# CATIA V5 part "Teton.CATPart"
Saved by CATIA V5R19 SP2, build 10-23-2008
Part number: Teton
Bounding box of the stored display mesh (mm): x 0 to 30, y -3.324 to 3.324, z -3.161 to 3.161
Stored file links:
  D:\SCHOOL\FRANCE\BANC_POUTRE_EN_MOUSSE\Teton.CATPart
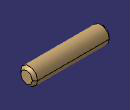
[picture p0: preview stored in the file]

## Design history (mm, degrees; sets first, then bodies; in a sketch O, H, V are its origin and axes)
AxisSystem1: origin (0, 0, 0), X (1, 0, 0), Y (0, 1, 0), Z (0, 0, 1)
Body1 (main body)
  Sketch1 on YZ plane of AxisSystem1, origin (0, 0, 0), H (0, 1, 0), V (0, 0, 1)
    circle A1 centre (0, 0) radius 3.324
    radius A1 = 3.324
  Pad1: profile Sketch1, direction (1, 0, 0), length 30
  Chamfer1: length 1, angle 45, on edge [face of Pad1 from Sketch1.A1 | end face of Pad1]
  Chamfer2: length 1, angle 45, on edge [start face of Pad1 | face of Pad1 from Sketch1.A1]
